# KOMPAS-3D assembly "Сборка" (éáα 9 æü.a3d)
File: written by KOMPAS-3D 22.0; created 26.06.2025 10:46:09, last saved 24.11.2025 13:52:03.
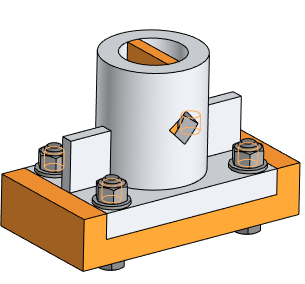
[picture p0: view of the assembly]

Document properties: Автор: Helen; Полное имя файла: C:\Для ноута\Инженерная графика\ППЭ 2025-2026\Варианты 1-38\Вариант 9 СБ\Вар 9 СБ\Вар 9 СБ.a3d

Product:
- Component [detail]: Сборка  | qty 4  | Масса: 0.008612; source file: Шайба 14.m3d
- Component [detail]: Сборка  | qty 4  | Масса: 0.02533; source file: Гайка М14.m3d
- Component [detail]: Болт М14x60 ГОСТ 15591-70  | qty 4  | Масса: 0.091885; source file: ..\..\Вариант 8 СБ\Вар 8 СБ\Болт М14x60 ГОСТ 15591-70.m3d
- Component [detail]: Основание  | designation Вариант 9  | qty 1  | Масса: 3.93188; source file: Основание вар 9.m3d
- Component [detail]: Nodes  | qty 1  | Масса: 4.387741; source file: Корпус вар 9.m3d
- Part/product: Сборка
    Масса: 8.822928

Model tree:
1. Массив по сетке:1  (with: Элемент выдавливания:5, Операция без истории:1, Элемент выдавливания:1)  (4 pattern instances)
     Шаг 1 = 120; Угол раствора = 90; Шаг 2 = 70

Referenced files in D:\MY\WORK\MPEI\ППЭ_2025-2026\Варианты\Вар 1 СБ\: Шайба 14.m3d, Гайка М14.m3d
Referenced files in C:\Для ноута\Инженерная графика\ППЭ 2025-2026\Варианты 1-38\Вариант 9 СБ\Вар 9 СБ\: Основание вар 9.m3d, Корпус вар 9.m3d
Referenced files in C:\Для ноута\Инженерная графика\ППЭ 2025-2026\Варианты 1-38\Вариант 8 СБ\Вар 8 СБ\: Болт М14x60 ГОСТ 15591-70.m3d
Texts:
  Сборка (1)
  Болт М14x60 ГОСТ 15591-70 (1)
  Вариант 9 Основание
